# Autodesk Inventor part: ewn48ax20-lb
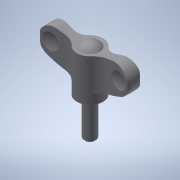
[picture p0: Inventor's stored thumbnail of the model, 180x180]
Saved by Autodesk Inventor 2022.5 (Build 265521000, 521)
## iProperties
Created: 2016-12
Part Number: ewn48ax20-lb
Material: 一般
Document SubType Name: Modeling
Designer: imaocorp
Density: 1 g/cm^3
Appearance: 既定
Author: imaocorp
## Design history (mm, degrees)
node "ewn48ax20-lb.x_t1"
node "ewn48ax20-lb"
node "Base1"
